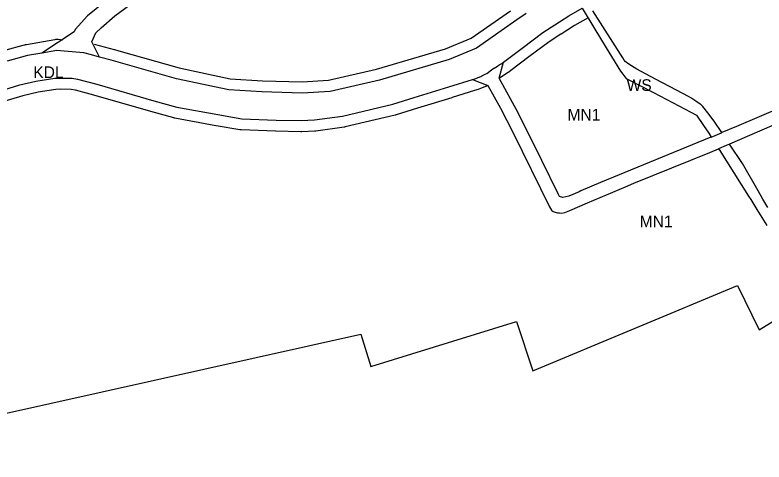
# Model space of a CAD drawing. Extents: x 7435758 to 7439981, y 5550649 to 5554049.
# Drawn here: x 7437108.2 to 7437442.5, y 5551399.2 to 5551598.7 of the extents above; entities that cross this region are included whole.
import ezdxf

# ---------------------------------------------------------------- set-up
doc = ezdxf.new("R2010")
doc.units = 0
for name, color, linetype in [('linie_rozgraniczające', 7, 'Continuous'), ('linie_zabudowy_nieprzekraczalne', 7, 'Continuous'), ('oznaczenia_przeznaczen', 7, 'Continuous')]:
    doc.layers.add(name, color=color, linetype=linetype)

msp = doc.modelspace()

# ---------------------------------------------------------------- linework, layer by layer
at = {"layer": 'linie_rozgraniczające'}
for p, q in [((7437152.75, 5551598.33), (7437163.32, 5551606.28)), ((7437148.34, 5551604.64), (7437140.56, 5551598.36)), ((7437336.26, 5551599.38), (7437332.17, 5551596.54)), ((7437355.37, 5551598.35), (7437361.33, 5551601.7)), ((7437361.33, 5551601.7), (7437366.52, 5551593.17)), ((7437379.39, 5551579.55), (7437366.07, 5551600.57)), ((7437140.56, 5551598.36), (7437135.1, 5551592.17)), ((7437146.74, 5551592.9), (7437152.75, 5551598.33)), ((7437332.17, 5551596.54), (7437314.16, 5551583.88)), ((7437349.17, 5551594.32), (7437355.37, 5551598.35)), ((7437144.31, 5551590.71), (7437146.74, 5551592.9)), ((7437343.75, 5551590.85), (7437349.17, 5551594.32)), ((7437366.52, 5551593.17), (7437366.52, 5551593.17)), ((7437366.52, 5551593.17), (7437372.04, 5551584.11)), ((7437134.63, 5551591.25), (7437120.27, 5551581.71)), ((7437135.1, 5551592.17), (7437134.63, 5551591.25)), ((7437142.54, 5551586.7), (7437144.31, 5551590.71)), ((7437334.59, 5551583.97), (7437343.75, 5551590.85)), ((7437146, 5551579.94), (7437142.54, 5551586.7)), ((7437126.93, 5551582.88), (7437120.27, 5551581.71)), ((7437130.14, 5551582.6), (7437126.93, 5551582.88)), ((7437138.9, 5551581.84), (7437130.14, 5551582.6)), ((7437314.16, 5551583.88), (7437301.93, 5551578.81)), ((7437326.16, 5551577.64), (7437334.59, 5551583.97)), ((7437372.04, 5551584.11), (7437374.39, 5551580.23)), ((7437113.83, 5551580.57), (7437104.79, 5551578.17)), ((7437120.27, 5551581.71), (7437113.83, 5551580.57)), ((7437142.42, 5551580.9), (7437138.9, 5551581.84)), ((7437146, 5551579.94), (7437142.42, 5551580.9)), ((7437151.21, 5551578.54), (7437146, 5551579.94)), ((7437374.39, 5551580.23), (7437378.36, 5551573.71)), ((7437380.02, 5551578.55), (7437379.39, 5551579.55)), ((7437180.35, 5551570.2), (7437151.21, 5551578.54)), ((7437301.93, 5551578.81), (7437270.84, 5551569.69)), ((7437322.12, 5551575.04), (7437323.49, 5551575.9)), ((7437323.49, 5551575.9), (7437324.29, 5551576.4)), ((7437324.29, 5551576.4), (7437325.13, 5551576.93)), ((7437324.31, 5551570.54), (7437326.16, 5551577.64)), ((7437325.13, 5551576.93), (7437325.63, 5551577.24)), ((7437325.63, 5551577.24), (7437326.16, 5551577.64)), ((7437380.45, 5551577.89), (7437380.02, 5551578.55)), ((7437382.18, 5551576.79), (7437380.45, 5551577.89)), ((7437385.68, 5551574.56), (7437382.18, 5551576.79)), ((7437318.02, 5551572.31), (7437318.72, 5551572.66)), ((7437318.72, 5551572.66), (7437320.93, 5551574.21)), ((7437320.93, 5551574.21), (7437321.93, 5551574.91)), ((7437321.93, 5551574.91), (7437322.12, 5551575.04)), ((7437378.36, 5551573.71), (7437380.95, 5551570.4)), ((7437389.87, 5551572.34), (7437385.68, 5551574.56)), ((7437110.46, 5551567.5), (7437117.56, 5551569.22)), ((7437117.56, 5551569.22), (7437125.97, 5551570.47)), ((7437125.97, 5551570.47), (7437128.49, 5551570.57)), ((7437128.49, 5551570.57), (7437133.74, 5551570.44)), ((7437133.74, 5551570.44), (7437136.2, 5551570.12)), ((7437136.2, 5551570.12), (7437144.72, 5551567.77)), ((7437203.64, 5551565.31), (7437180.35, 5551570.2)), ((7437270.84, 5551569.69), (7437248.84, 5551564.61)), ((7437301.76, 5551566.59), (7437312.34, 5551569.89)), ((7437312.34, 5551569.89), (7437313.36, 5551570.21)), ((7437312.34, 5551569.89), (7437319.26, 5551567.28)), ((7437313.36, 5551570.21), (7437316.05, 5551571.3)), ((7437316.05, 5551571.3), (7437316.53, 5551571.55)), ((7437316.53, 5551571.55), (7437316.89, 5551571.73)), ((7437316.89, 5551571.73), (7437317.46, 5551572.02)), ((7437317.46, 5551572.02), (7437318.02, 5551572.31)), ((7437332.79, 5551555.04), (7437324.31, 5551570.54)), ((7437380.95, 5551570.4), (7437393.08, 5551564.08)), ((7437394.02, 5551570.14), (7437389.87, 5551572.34)), ((7437403.46, 5551565.14), (7437394.02, 5551570.14)), ((7437100.72, 5551564.52), (7437110.46, 5551567.5)), ((7437144.72, 5551567.77), (7437170.23, 5551560.45)), ((7437286.32, 5551561.87), (7437301.76, 5551566.59)), ((7437319.26, 5551567.28), (7437324.83, 5551557.11)), ((7437218.4, 5551564.39), (7437203.64, 5551565.31)), ((7437236.44, 5551563.85), (7437218.4, 5551564.39)), ((7437248.84, 5551564.61), (7437236.44, 5551563.85)), ((7437393.08, 5551564.08), (7437404.43, 5551558.15)), ((7437408.72, 5551562.36), (7437403.46, 5551565.14)), ((7437461.88, 5551562.63), (7437430.21, 5551548.94)), ((7437170.23, 5551560.45), (7437180.41, 5551557.58)), ((7437276.79, 5551558.9), (7437286.32, 5551561.87)), ((7437409.85, 5551561.76), (7437408.72, 5551562.36)), ((7437412.01, 5551560.28), (7437409.85, 5551561.76)), ((7437414.01, 5551558.9), (7437412.01, 5551560.28)), ((7437180.41, 5551557.58), (7437198.76, 5551554.23)), ((7437254.38, 5551553.62), (7437276.79, 5551558.9)), ((7437324.83, 5551557.11), (7437330.51, 5551546.19)), ((7437404.43, 5551558.15), (7437412.38, 5551554.01)), ((7437414.48, 5551558.57), (7437414.01, 5551558.9)), ((7437415.09, 5551557.81), (7437414.48, 5551558.57)), ((7437417.36, 5551554.99), (7437415.09, 5551557.81)), ((7437464.28, 5551557.13), (7437427.1, 5551541.11)), ((7437198.76, 5551554.23), (7437209.4, 5551552.42)), ((7437209.4, 5551552.42), (7437224.7, 5551551.82)), ((7437241.83, 5551551.89), (7437254.38, 5551553.62)), ((7437336.1, 5551548.42), (7437332.79, 5551555.04)), ((7437412.38, 5551554.01), (7437415.49, 5551549.39)), ((7437420.26, 5551551.36), (7437417.36, 5551554.99)), ((7437224.7, 5551551.82), (7437235.9, 5551551.58)), ((7437235.9, 5551551.58), (7437241.83, 5551551.89)), ((7437415.49, 5551549.39), (7437417.77, 5551546.01)), ((7437423.69, 5551546.25), (7437420.26, 5551551.36)), ((7437330.51, 5551546.19), (7437346.78, 5551513.13)), ((7437339.76, 5551541.13), (7437336.1, 5551548.42)), ((7437417.77, 5551546.01), (7437418.85, 5551544.26)), ((7437418.85, 5551544.26), (7437423.43, 5551546.15)), ((7437423.43, 5551546.15), (7437423.69, 5551546.25)), ((7437430.21, 5551548.94), (7437423.69, 5551546.25)), ((7437418.77, 5551544.23), (7437369.52, 5551523.95)), ((7437418.82, 5551544.25), (7437418.77, 5551544.23)), ((7437418.85, 5551544.26), (7437418.82, 5551544.25)), ((7437343.39, 5551533.72), (7437339.76, 5551541.13)), ((7437418.23, 5551537.33), (7437422.16, 5551539)), ((7437425.64, 5551540.48), (7437422.16, 5551539)), ((7437422.16, 5551539), (7437422.37, 5551538.67)), ((7437422.16, 5551539), (7437422.16, 5551539)), ((7437427.04, 5551541.08), (7437425.64, 5551540.48)), ((7437427.1, 5551541.11), (7437427.04, 5551541.08)), ((7437432.81, 5551532.41), (7437427.1, 5551541.11)), ((7437384.42, 5551523.61), (7437418.23, 5551537.33)), ((7437422.37, 5551538.67), (7437422.38, 5551538.67)), ((7437422.38, 5551538.67), (7437435.56, 5551517.84)), ((7437350.62, 5551518.94), (7437343.39, 5551533.72)), ((7437439.88, 5551520.22), (7437432.81, 5551532.41)), ((7437369.52, 5551523.95), (7437360.76, 5551520.19)), ((7437380.59, 5551522), (7437384.42, 5551523.61)), ((7437351.2, 5551517.75), (7437350.62, 5551518.94)), ((7437360.03, 5551519.87), (7437355.36, 5551517.87)), ((7437360.76, 5551520.19), (7437360.03, 5551519.87)), ((7437363.69, 5551514.91), (7437380.59, 5551522)), ((7437442, 5551516.56), (7437439.88, 5551520.22)), ((7437352.67, 5551517.2), (7437351.2, 5551517.75)), ((7437355.36, 5551517.87), (7437352.67, 5551517.2)), ((7437435.56, 5551517.84), (7437435.56, 5551517.84)), ((7437435.56, 5551517.84), (7437436.51, 5551516.34)), ((7437436.51, 5551516.34), (7437439.31, 5551511.91)), ((7437444.13, 5551512.88), (7437442, 5551516.56)), ((7437346.78, 5551513.13), (7437347.62, 5551511.61)), ((7437355.79, 5551511.52), (7437363.69, 5551514.91)), ((7437347.62, 5551511.61), (7437348.36, 5551510.97)), ((7437348.36, 5551510.97), (7437349.71, 5551510.54)), ((7437349.71, 5551510.54), (7437350.29, 5551510.49)), ((7437350.29, 5551510.49), (7437351.14, 5551510.43)), ((7437351.14, 5551510.43), (7437352.21, 5551510.35)), ((7437352.21, 5551510.35), (7437353.61, 5551510.59)), ((7437353.61, 5551510.59), (7437355.79, 5551511.52)), ((7437439.31, 5551511.91), (7437443.68, 5551504.82)), ((7437339.37, 5551439.87), (7437430.62, 5551478.01)), ((7437430.62, 5551478.01), (7437440.33, 5551458.26)), ((7437440.33, 5551458.26), (7437463.55, 5551472.55)), ((7437267.01, 5551441.82), (7437332, 5551461.92)), ((7437332, 5551461.92), (7437339.37, 5551439.87)), ((7437006.21, 5551399.25), (7437262.51, 5551456.29)), ((7437262.51, 5551456.29), (7437267.01, 5551441.82))]:
    msp.add_line(p, q, dxfattribs=at)
at = {"layer": 'linie_zabudowy_nieprzekraczalne'}
for points in [[(7437143.63, 5551585.75), (7437152.51, 5551583.36), (7437152.59, 5551583.34), (7437154.55, 5551582.78), (7437181.55, 5551575.06), (7437204.32, 5551570.28), (7437218.63, 5551569.38), (7437236.36, 5551568.85), (7437248.12, 5551569.57), (7437269.57, 5551574.52), (7437300.27, 5551583.54), (7437311.74, 5551588.29), (7437329.3, 5551600.63)], [(7437364, 5551597.47), (7437357.96, 5551594.07), (7437351.89, 5551590.13), (7437351.86, 5551590.11), (7437346.6, 5551586.74), (7437337.59, 5551579.97), (7437329.53, 5551573.92), (7437328.63, 5551573.25), (7437328.57, 5551573.2), (7437328.3, 5551573.02), (7437328.29, 5551573.01), (7437324.88, 5551570.87), (7437324.34, 5551570.49)], [(7437104.3, 5551583.22), (7437111.87, 5551585.22), (7437112.65, 5551585.43), (7437112.65, 5551585.43), (7437112.95, 5551585.49), (7437113.03, 5551585.51), (7437113.43, 5551585.58), (7437126.07, 5551587.81), (7437126.09, 5551587.81), (7437126.4, 5551587.85), (7437126.41, 5551587.85), (7437126.7, 5551587.87), (7437126.74, 5551587.88), (7437127.05, 5551587.88), (7437127.06, 5551587.88), (7437127.35, 5551587.86), (7437127.44, 5551587.85), (7437129.58, 5551587.67)], [(7437319.24, 5551567.31), (7437318.32, 5551566.84), (7437318.14, 5551566.76), (7437317.92, 5551566.66), (7437315.24, 5551565.57), (7437315.16, 5551565.54), (7437314.85, 5551565.44), (7437313.32, 5551564.96), (7437303.25, 5551561.82), (7437303.22, 5551561.81), (7437287.79, 5551557.09), (7437278.28, 5551554.13), (7437277.97, 5551554.04), (7437277.94, 5551554.03), (7437255.53, 5551548.75), (7437255.24, 5551548.69), (7437255.07, 5551548.67), (7437242.52, 5551546.93), (7437242.36, 5551546.91), (7437242.09, 5551546.89), (7437236.16, 5551546.58), (7437236.1, 5551546.58), (7437235.79, 5551546.58), (7437224.59, 5551546.82), (7437224.58, 5551546.82), (7437224.51, 5551546.82), (7437209.2, 5551547.43), (7437208.95, 5551547.44), (7437208.62, 5551547.48), (7437208.56, 5551547.49), (7437197.93, 5551549.3), (7437197.87, 5551549.31), (7437179.52, 5551552.66), (7437179.32, 5551552.7), (7437179.05, 5551552.76), (7437168.87, 5551555.64), (7437168.85, 5551555.64), (7437143.37, 5551562.96), (7437135.21, 5551565.2), (7437133.35, 5551565.45), (7437128.52, 5551565.57), (7437126.44, 5551565.49), (7437118.52, 5551564.31), (7437111.79, 5551562.68), (7437102.24, 5551559.75)]]:
    msp.add_lwpolyline(points, dxfattribs=at)

# ---------------------------------------------------------------- texts
at = {"layer": 'oznaczenia_przeznaczen'}
for s, p in [('KDL', (7437116.39, 5551570.56)), ('WS', (7437381.14, 5551564.82)), ('MN1', (7437354.76, 5551551.62)), ('MN1', (7437386.99, 5551503.98))]:
    msp.add_text(s, height=5.2, dxfattribs=at).set_placement(p)

doc.saveas('drawing.dxf')
